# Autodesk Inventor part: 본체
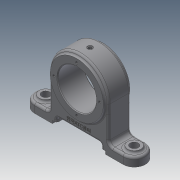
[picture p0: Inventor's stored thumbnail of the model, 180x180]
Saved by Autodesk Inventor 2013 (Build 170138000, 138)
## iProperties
Created: 2019-05
Part Number: 본체
Material: 일반
Document SubType Name: Modeling
Designer: 00
Density: 1 g/cm^3
Author: 00
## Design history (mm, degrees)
sketch "스케치1"
  geometry: L1 (-40, -60)-(40, -60); L2 (40, -60)-(40, 0); L3 (40, 0)-(-40, 0); L4 (-40, 0)-(-40, -60); C1 r 40 at (0, 0); 1 further point
  constraints: 8 end point, 2 midpoint, 2 parallel, 1 centre point, 1 coincident, 1 horizontal, 1 perpendicular
  dimensions: "d0" = 80 distance of L3.end L2.end; "d1" = 60 distance of L2.end L1.end; "d3" = 80 diameter of C1
extrude "돌출1" new body sketch "스케치1" stored distance "d4" = 30; taper "d5" = 0 deg
sketch "스케치2"
  geometry: C1 r 36 at (0, 0); 1 further point
  constraints: 1 centre point, 1 coincident
  dimensions: "d6" = 72 diameter of C1
extrude "돌출2" join sketch "스케치2" stored distance "d7" = 36; taper "d8" = 0 deg
sketch "스케치3"
  geometry: C1 r 36 at (0, 0) reference; C2 r 26 at (0, 0)
  constraints: 1 centre point, 1 coincident
  dimensions: "d9" = 52 diameter of C2
extrude "돌출3" cut sketch "스케치3" stored distance "d10" = 36; taper "d11" = 0 deg
sketch "스케치4"
  geometry: L1 (0, 0)-(0, 31); C1 r 36 at (0, 0) reference; 1 further point
  constraints: 2 end point, 1 coincident, 1 vertical
  dimensions: "d12" = 31 distance of L1.start L1.end
hole "구멍1" sketch "스케치4" at (0, 31) diameter "d13" = 3.242; stored, may be unused: countersink angle "d17" = 90 deg, drill point angle "d19" = 118 deg; dims "d14" = 6, "d15" = 4, "d16" = 2, "d18" = 8
node "작업 평면1"
sketch "스케치5"
  geometry: 2 further points
  constraints: 1 coincident
hole "구멍2" sketch "스케치5" at (0, 0) diameter "d24" = 4.917; stored, may be unused: countersink angle "d28" = 90 deg, drill point angle "d30" = 118 deg; dims "d25" = 8, "d26" = 7, "d27" = 1, "d29" = 10
sketch "스케치6"
  geometry: L1 (80, -30)-(80, 0) reference; L2 (0, 0)-(80, 0) reference; L3 (0, 0)-(0, -30) reference; L4 (80, -30)-(0, -30) reference; L5 (100, -30)-(-20, -30); L6 (-20, -30)-(-20, 0); L7 (-20, 0)-(100, 0); L8 (100, 0)-(100, -30); L9 (100, -30)-(-20, 0); L10 (-20, -30)-(100, 0); C1 r 15 at (-20, -15); C2 r 15 at (100, -15); 1 further point
  constraints: 12 end point, 4 midpoint, 2 centre point, 2 parallel, 1 horizontal, 1 perpendicular
  dimensions: "d31" = 120 distance of L6.end L7.end; "d32" = 30 distance of L5.end L6.end; "d33" = 30 diameter of C1; "d34" = 30 diameter of C2
extrude "돌출4" join sketch "스케치6" distance "d35" = 12; taper "d36" = 0 deg
sketch "스케치7"
  geometry: C1 r 9 at (-20, 15); A1 r 15 centre (-20, 15) between (-20, 30) and (-20, 0) reference; 1 further point
  constraints: 1 centre point, 1 coincident
  dimensions: "d37" = 18 diameter of C1
extrude "돌출5" join sketch "스케치7" distance "d38" = 3; taper "d39" = 0 deg
sketch "스케치8"
  geometry: C1 r 9 at (0, 0) reference; 2 further points
  constraints: 1 coincident
hole "구멍3" sketch "스케치8" at (0, 0) diameter "d40" = 11; stored, may be unused: countersink angle "d44" = 90 deg, drill point angle "d46" = 118 deg; dims "d41" = 8, "d42" = 7, "d43" = 1, "d45" = 10
sketch "스케치9"
  geometry: L1 (-60, -60)-(60, -60) reference; L2 (-36, -60)-(36, -60); L3 (36, -60)-(36, -56); L4 (36, -56)-(-36, -56); L5 (-36, -56)-(-36, -60); 1 further point
  constraints: 8 end point, 2 midpoint, 2 parallel, 1 horizontal, 1 perpendicular
  dimensions: "d47" = 72 distance of L4.end L3.end; "d48" = 4 distance of L3.end L2.end
extrude "돌출6" cut sketch "스케치9" stored distance "d49" = 3; taper "d50" = 0 deg
sketch "스케치10"
  geometry: L1 (-36, -56)-(36, -56) reference; L2 (-30, -56)-(30, -56); L3 (30, -56)-(30, -50); L4 (30, -50)-(-30, -50); L5 (-30, -50)-(-30, -56); 1 further point
  constraints: 8 end point, 2 midpoint, 2 parallel, 1 horizontal, 1 perpendicular
  dimensions: "d51" = 60 distance of L4.end L3.end; "d52" = 6 distance of L3.end L2.end
extrude "돌출7" cut sketch "스케치10" stored distance "d53" = 3; taper "d54" = 0 deg
node "작업 평면2"
sketch "스케치11"
  geometry: 2 further points
  constraints: 1 coincident
hole "구멍4" sketch "스케치11" at (0, 0) diameter "d56" = 2; stored, may be unused: countersink angle "d60" = 90 deg, drill point angle "d62" = 118 deg; dims "d57" = 8, "d58" = 7, "d59" = 1, "d61" = 10
sketch "스케치12"
  geometry: C1 r 1.5 at (0, 26); 1 further point
  constraints: 2 vertical alignment, 1 centre point, 1 other
  dimensions: "d63" = 3 diameter of C1
extrude "돌출8" cut sketch "스케치12" stored distance "d64" = 3; taper "d65" = 0 deg
chamfer "모따기1" distance "d66" = 1; stored, may be unused: second distance "d67" = 2, angle "d68" = 45 deg
fillet "모깎기1" dims "d69" = 6
sketch "스케치13"
  geometry: L1 (-30, -50)-(30, -50) reference; A1 r 40 centre (0, 0) between (40, 0) and (-40, 0) reference; 1 further point
  constraints: 1 vertical alignment, 1 other
  dimensions: "d70" = 7 distance from line of point (0, -43) L1
feature "엠보싱1" sketch "스케치13" dims "d0" = 80, "d1" = 60, "d71" = 0.5, "d72" = 0
fillet "모깎기2" dims "d73" = 3
fillet "모깎기3" dims "d74" = 3
fillet "모깎기4" dims "d75" = 3
fillet "모깎기5" dims "d76" = 3
node "솔리드1"
pattern_circular "원형 패턴1" dims angle "d21" = 360 deg
mirror "대칭1"
mirror "대칭2"
other parameters: "d55" = 26
